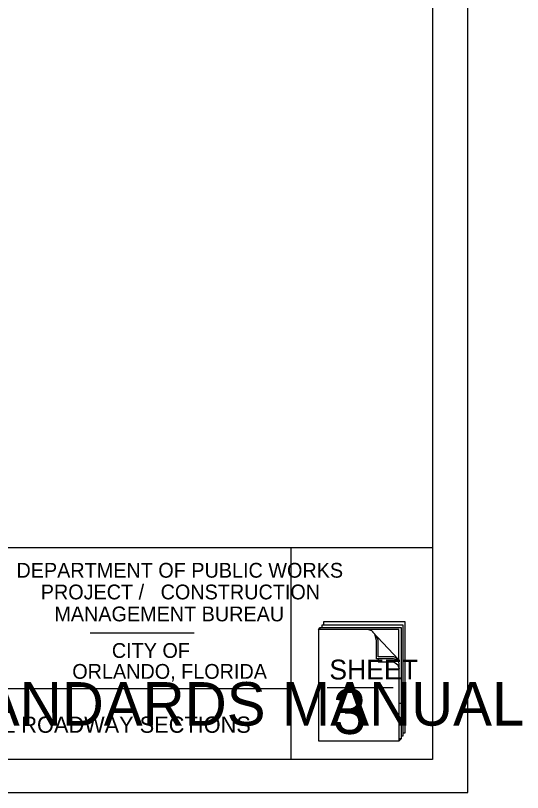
# Model space of a CAD drawing. Extents: x 29.7 to 46.4, y -39.2 to -28.2.
# Drawn here: x 42.83 to 46.42, y -39.2 to -33.7 of the extents above; entities that cross this region are included whole.
import ezdxf

# ---------------------------------------------------------------- set-up
doc = ezdxf.new("R2010")
doc.units = 0
doc.layers.add('Level 60', color=7, linetype='Continuous')
doc.layers.add('Level 62', color=7, linetype='Continuous')

msp = doc.modelspace()

# ---------------------------------------------------------------- linework, layer by layer
at = {"layer": 'Level 60'}
for p, q in [((44.0946, -38.072), (43.3581, -38.072)), ((45.3572, -38.0609), (45.541, -38.2581)), ((45.5245, -38.2455), (45.5425, -38.2593))]:
    msp.add_line(p, q, dxfattribs=at)
for points in [[(29.7027, -39.1993), (46.0327, -39.1993), (46.0327, -28.1926), (29.7027, -28.1926)], [(30.3565, -28.4094), (45.7818, -28.4094), (45.7818, -38.965), (30.3565, -38.965)], [(45.5434, -38.0448), (45.3695, -38.0448), (45.3246, -38.045), (44.9735, -38.045), (44.9865, -38.0301), (45.5586, -38.0301), (45.5586, -38.8192), (45.5456, -38.834), (45.5456, -38.3484), (45.5456, -38.2926), (45.5422, -38.2729), (45.5434, -38.2315)], [(44.9735, -38.834), (45.5456, -38.834), (45.5456, -38.3484), (45.5456, -38.3176), (45.5456, -38.2926), (45.5456, -38.2926), (45.5422, -38.2729), (45.531, -38.2609), (45.5066, -38.2516), (45.3847, -38.2516), (45.3847, -38.1232), (45.3729, -38.0777), (45.3519, -38.0553), (45.3246, -38.045), (44.9735, -38.045)], [(45.3964, -38.2521), (45.3964, -38.2746), (45.4963, -38.2746), (45.5082, -38.2766), (45.5179, -38.2807), (45.5273, -38.2876), (45.5351, -38.2955), (45.5393, -38.3042), (45.5456, -38.3245), (45.5454, -38.2914), (45.5422, -38.2729), (45.531, -38.2609), (45.5066, -38.2516)]]:
    msp.add_lwpolyline(points, close=True, dxfattribs=at)
for points in [[(45.7822, -37.4656), (41.923, -37.4656)], [(44.7811, -38.9652), (44.7811, -37.4656)], [(44.9995, -38.0301), (44.9995, -38.0115), (45.5716, -38.0115), (45.5716, -38.8005), (45.5586, -38.8005)], [(45.0125, -38.0115), (45.0125, -37.9892), (45.5846, -37.9892), (45.5846, -38.7782), (45.5716, -38.7782)], [(44.9865, -38.045), (44.9865, -38.0301), (45.5586, -38.0301), (45.5586, -38.8192), (45.5456, -38.8192)], [(45.5245, -38.2455), (45.5087, -38.2394), (45.3964, -38.2394), (45.3964, -38.1213), (45.3882, -38.0942)], [(44.7811, -38.4653), (41.923, -38.4653)], [(45.0362, -38.4554), (45.504, -38.4554)], [(45.5606, -38.57), (45.5476, -38.57)]]:
    msp.add_lwpolyline(points, dxfattribs=at)

# ---------------------------------------------------------------- texts
for s, height, p in [('DEPARTMENT OF PUBLIC WORKS', 0.104776, (42.8368, -37.6779)), ('PROJECT /   CONSTRUCTION', 0.104776, (43.0087, -37.8315)), ('MANAGEMENT BUREAU', 0.104773, (43.1048, -37.9871)), ('CITY OF', 0.10477, (43.5121, -38.2461)), ('ORLANDO, FLORIDA', 0.104773, (43.2319, -38.3942)), ('SHEET', 0.14055, (45.0516, -38.3991)), ('ENGINEERING STANDARDS MANUAL', 0.308157, (39.0591, -38.7259)), ('3 ', 0.31932, (45.0762, -38.785))]:
    msp.add_text(s, height=height, dxfattribs=at).set_placement(p)
at = {"layer": 'Level 62'}
msp.add_text('TYPICAL ROADWAY SECTIONS', height=0.115042, dxfattribs=at).set_placement((42.1876, -38.7767))

doc.saveas('drawing.dxf')
